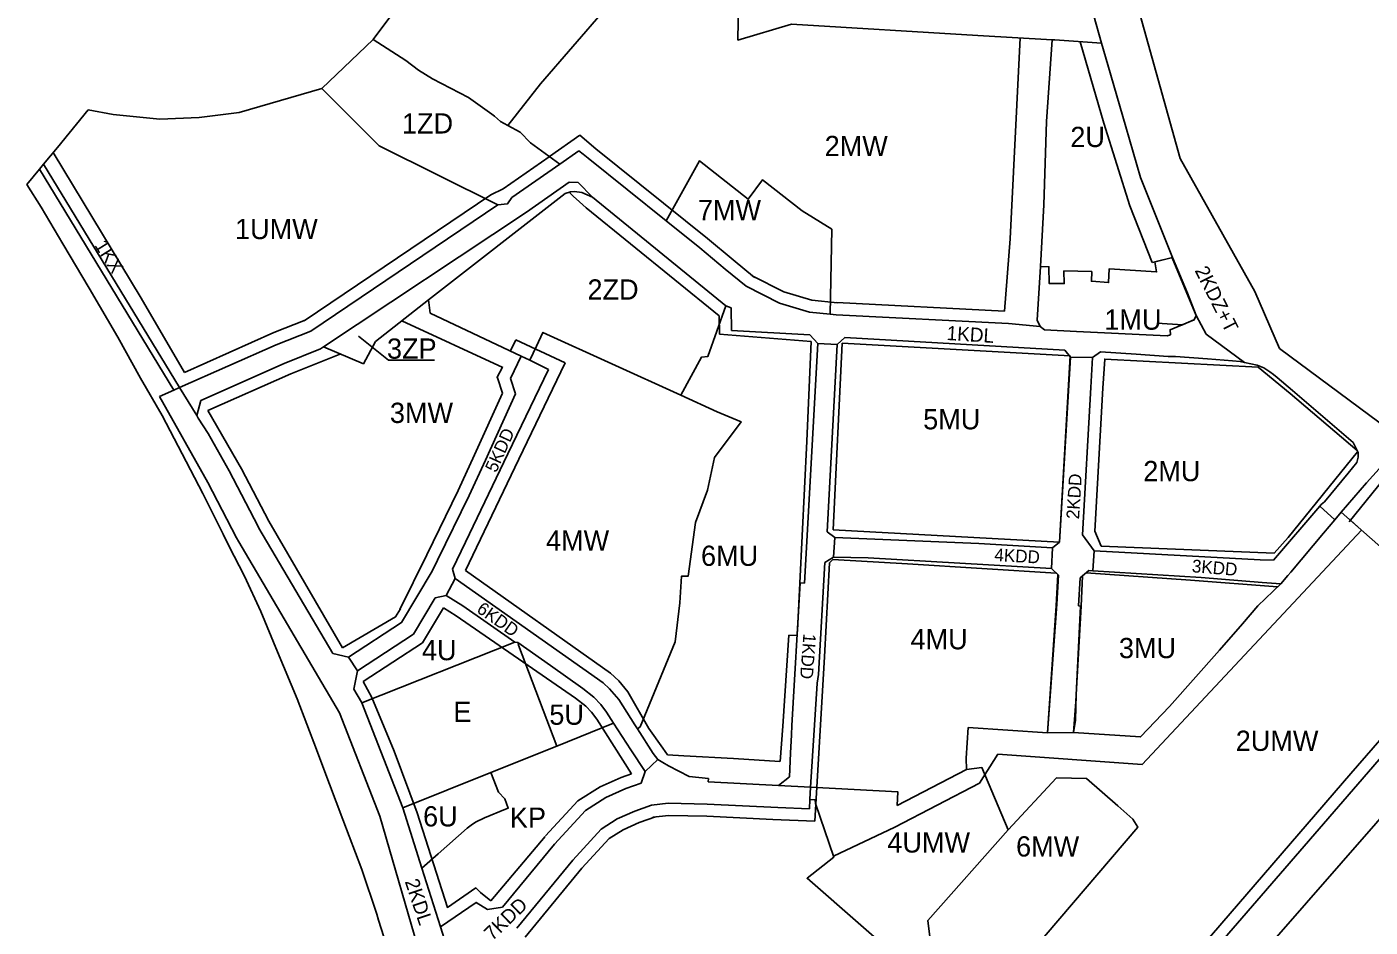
# Model space of a CAD drawing. Extents: x 7426210 to 7427579, y 5548413 to 5549685.
# Drawn here: x 7426454 to 7427118, y 5548687 to 5549132 of the extents above; entities that cross this region are included whole.
import ezdxf

# ---------------------------------------------------------------- set-up
doc = ezdxf.new("R2010")
doc.units = 0
for name, color, linetype in [('linie_rozgraniczajace', 7, 'Continuous'), ('linie_zabudowy_nieprzekraczalne', 7, 'Continuous'), ('linie_zabudowy_obowiazujace', 7, 'Continuous'), ('oznaczenia_przeznaczen', 7, 'Continuous')]:
    doc.layers.add(name, color=color, linetype=linetype)

msp = doc.modelspace()

# ---------------------------------------------------------------- linework, layer by layer
at = {"layer": 'linie_rozgraniczajace'}
for p, q in [((7426717.76, 5549064.39), (7426727.22, 5549070.95)), ((7426527.12, 5548952.75), (7426460.67, 5549061.87)), ((7426461.46, 5549043.11), (7426454.42, 5549054.29)), ((7426722.33, 5549055.38), (7426726.85, 5549055.19)), ((7426733.96, 5549047.99), (7426726.85, 5549055.19)), ((7426652.81, 5548997.28), (7426720.48, 5549049.79)), ((7426472.27, 5549025.01), (7426461.46, 5549043.11)), ((7426687.05, 5549044.16), (7426594.8, 5548981.91)), ((7426485.27, 5549003.09), (7426472.27, 5549025.01)), ((7426499.3, 5548978.86), (7426485.27, 5549003.09)), ((7426809.75, 5549004.04), (7426826.24, 5548995.73)), ((7426826.24, 5548995.73), (7426841.15, 5548991.24)), ((7426841.25, 5548980.07), (7426802.56, 5548982.08)), ((7426510.62, 5548958.68), (7426499.3, 5548978.86)), ((7426838.66, 5548857.41), (7426845.26, 5548975.81)), ((7426845.26, 5548975.81), (7426841.25, 5548980.07)), ((7426845.26, 5548975.81), (7426854.77, 5548975.24)), ((7426698.72, 5548969.45), (7426693.37, 5548958.37)), ((7426702.96, 5548967.44), (7426712.24, 5548962.96)), ((7426981.03, 5548968.79), (7426970.11, 5548968.93)), ((7426712.24, 5548962.96), (7426692.09, 5548921.26)), ((7426521.3, 5548940.19), (7426510.62, 5548958.68)), ((7426695.91, 5548950.88), (7426693.37, 5548958.37)), ((7426540.34, 5548947.65), (7426538.34, 5548940.09)), ((7426531.22, 5548921.19), (7426521.3, 5548940.19)), ((7426541.32, 5548901.7), (7426531.22, 5548921.19)), ((7426692.09, 5548921.26), (7426671.17, 5548877.55)), ((7427111.6, 5548916.93), (7427107.32, 5548911.74)), ((7427107.32, 5548911.74), (7427095.62, 5548897.58)), ((7426551.35, 5548881.59), (7426541.32, 5548901.7)), ((7427100.68, 5548888.63), (7427093.22, 5548895.38)), ((7427095.62, 5548897.58), (7427093.87, 5548896.14)), ((7427100.68, 5548888.63), (7427103.85, 5548892.38)), ((7427103.85, 5548892.38), (7427170.23, 5548833.74)), ((7426554.28, 5548875.85), (7426551.35, 5548881.59)), ((7426975.99, 5548881.15), (7426981.75, 5548873.39)), ((7426561.93, 5548860.88), (7426554.28, 5548875.85)), ((7426671.17, 5548877.55), (7426664.8, 5548864.29)), ((7426853.57, 5548879.94), (7426853.05, 5548870.2)), ((7426960.68, 5548864.59), (7426961.26, 5548874.85)), ((7426853.05, 5548870.2), (7426848.73, 5548867.55)), ((7426870.1, 5548869.79), (7426853.05, 5548870.2)), ((7426960.68, 5548864.59), (7426870.1, 5548869.79)), ((7426981.75, 5548873.39), (7426981.12, 5548863.46)), ((7427063.78, 5548868.85), (7426981.75, 5548873.39)), ((7427070.41, 5548868.79), (7427063.78, 5548868.85)), ((7426666.12, 5548859.71), (7426664.8, 5548864.29)), ((7426848.73, 5548867.55), (7426845.58, 5548812.16)), ((7426964.12, 5548861.22), (7426960.68, 5548864.59)), ((7426963.41, 5548847.03), (7426964.12, 5548861.22)), ((7426979.1, 5548863.59), (7426974.87, 5548859.97)), ((7426570.05, 5548843.37), (7426561.93, 5548860.88)), ((7426666.12, 5548859.71), (7426661.62, 5548851.3)), ((7426666.12, 5548859.71), (7426739.25, 5548808.06)), ((7426832.44, 5548787.03), (7426836.59, 5548857.53)), ((7426836.59, 5548857.53), (7426838.66, 5548857.41)), ((7426974.87, 5548859.97), (7426973.99, 5548846.1)), ((7427064.8, 5548857.72), (7427034.65, 5548860.08)), ((7427064.8, 5548857.72), (7427073.97, 5548857.02)), ((7426661.62, 5548851.3), (7426656.21, 5548850.12)), ((7426578.26, 5548823.43), (7426570.05, 5548843.37)), ((7426958.69, 5548783.49), (7426963.41, 5548847.03)), ((7426974.96, 5548846), (7426972.73, 5548798.8)), ((7426973.99, 5548846.1), (7426974.96, 5548846)), ((7426695.45, 5548828.16), (7426619.85, 5548798.2)), ((7426587.94, 5548800.28), (7426578.26, 5548823.43)), ((7426617.79, 5548814.08), (7426613.33, 5548820.73)), ((7426739.25, 5548808.06), (7426742.33, 5548805.11)), ((7426844.99, 5548807.88), (7426845.58, 5548812.16)), ((7426742.33, 5548805.11), (7426746.84, 5548799.85)), ((7426844.98, 5548807.79), (7426844.99, 5548807.88)), ((7426597.52, 5548775.14), (7426587.94, 5548800.28)), ((7426746.84, 5548799.85), (7426754.9, 5548787.34)), ((7426972.73, 5548798.8), (7426971.6, 5548783.55)), ((7426716.2, 5548776.82), (7426744.32, 5548788.26)), ((7426757.38, 5548786.32), (7426756.09, 5548785.44)), ((7426831.75, 5548773.37), (7426832.2, 5548782.47)), ((7426832.2, 5548782.47), (7426832.44, 5548787.03)), ((7426971.6, 5548783.55), (7426958.69, 5548783.49)), ((7426600.66, 5548766.86), (7426597.52, 5548775.14)), ((7426752.87, 5548774.94), (7426759.87, 5548764.39)), ((7426759.87, 5548764.39), (7426766.15, 5548770.31)), ((7426763.8, 5548773.21), (7426766.15, 5548770.31)), ((7426766.15, 5548770.31), (7426768.7, 5548768.7)), ((7426768.7, 5548768.7), (7426771.42, 5548767.16)), ((7426831.17, 5548761.72), (7426831.75, 5548773.37)), ((7426918.53, 5548770.92), (7426918.65, 5548765.3)), ((7426610.61, 5548740.55), (7426600.66, 5548766.86)), ((7426759.87, 5548764.39), (7426757.92, 5548758.55)), ((7426825.78, 5548757.39), (7426831.17, 5548761.72)), ((7426884.49, 5548747.6), (7426918.65, 5548765.3)), ((7426740.49, 5548751.49), (7426750.31, 5548755.85)), ((7426750.31, 5548755.85), (7426757.92, 5548758.55)), ((7426730.47, 5548745.13), (7426740.49, 5548751.49)), ((7426652.39, 5548661.45), (7426628.81, 5548742.31)), ((7426715.11, 5548728.46), (7426730.47, 5548745.13)), ((7426825.4, 5548746.48), (7426841.05, 5548745.82)), ((7426620, 5548715.87), (7426610.61, 5548740.55)), ((7426689.51, 5548697.37), (7426715.11, 5548728.46)), ((7426627.28, 5548693.92), (7426620, 5548715.87)), ((7426682.07, 5548696.12), (7426689.51, 5548697.37)), ((7426628.23, 5548690.91), (7426627.28, 5548693.92)), ((7426630.8, 5548682.71), (7426628.23, 5548690.91))]:
    msp.add_line(p, q, dxfattribs=at)
for points in [[(7426962.26, 5549289.73), (7427024.27, 5549067.18), (7427061.13, 5549001.37), (7427073.43, 5548973.27), (7427176.69, 5548896.63)], [(7426454.42, 5549054.29), (7426460.61, 5549061.8), (7426460.67, 5549061.87), (7426462.69, 5549064.32), (7426469.52, 5549072.6), (7426484.77, 5549091.08), (7426496.98, 5549088.91), (7426520.12, 5549086.53), (7426539.6, 5549087.43), (7426559.4, 5549089.83), (7426600.21, 5549101.71), (7426625.56, 5549125.89), (7426648.85, 5549157.31)], [(7426975.38, 5549159.04), (7426981.57, 5549137.62), (7426985.46, 5549124.17), (7426988.6, 5549113.31), (7426997.45, 5549082.71), (7427004.65, 5549057.71), (7427020.44, 5549018.16), (7427027.82, 5549000.62), (7427032.23, 5548989.61)], [(7426740.22, 5549140.87), (7426708.13, 5549104.02), (7426692.04, 5549083.48)], [(7426985.46, 5549124.17), (7426962.3, 5549125.67), (7426961.04, 5549125.75), (7426924.29, 5549127.91), (7426832.21, 5549133.53), (7426805.72, 5549125.65), (7426806.11, 5549144.19)], [(7426684.2, 5549089.06), (7426672.66, 5549097.33), (7426654.78, 5549106.46), (7426648, 5549110.74), (7426641.61, 5549115.5), (7426625.56, 5549125.89)], [(7426961.04, 5549125.75), (7426958.22, 5549085.37), (7426956.97, 5549044.24), (7426955.19, 5549013.78), (7426953.65, 5548987.32), (7426955.03, 5548984.12), (7426957.27, 5548982.52), (7426973.08, 5548981.74), (7427017.93, 5548979.45), (7427019.48, 5548980.04), (7427019.27, 5548982.5), (7427031.27, 5548987.37), (7427032.23, 5548989.61)], [(7426600.21, 5549101.71), (7426628.44, 5549073.4), (7426687.05, 5549044.16), (7426691.94, 5549044.79), (7426694.07, 5549047.79), (7426717.76, 5549064.39)], [(7426684.2, 5549089.06), (7426685.56, 5549088.09), (7426688.48, 5549085.44), (7426692.04, 5549083.48), (7426698.19, 5549080.13), (7426703.24, 5549074.83), (7426717.76, 5549064.39)], [(7426727.22, 5549070.95), (7426729.35, 5549069.31), (7426731.7, 5549067.32), (7426770.32, 5549036.39), (7426786.99, 5549023.04), (7426799.5, 5549012.47), (7426809.75, 5549004.04)], [(7426529.89, 5548953.97), (7426462.69, 5549064.32)], [(7426837.48, 5549041.19), (7426817.84, 5549056.54), (7426810.85, 5549047.01), (7426786.72, 5549065.89), (7426770.32, 5549036.39)], [(7426701.22, 5549040.59), (7426722.33, 5549055.38)], [(7426799.84, 5548994.31), (7426733.96, 5549047.99), (7426728.71, 5549050.28), (7426725.07, 5549050.87), (7426723, 5549050.66), (7426720.48, 5549049.79)], [(7426701.22, 5549040.59), (7426601.02, 5548974.03), (7426599.5, 5548973.02)], [(7426837.48, 5549041.19), (7426852.13, 5549032.15), (7426851.32, 5548990.21)], [(7427020.44, 5549018.16), (7427011.82, 5549016.12), (7427012.65, 5549011.1), (7426989.24, 5549012.63), (7426988.87, 5549005.85), (7426980.4, 5549006.51), (7426980.59, 5549011.23), (7426966.85, 5549011.61), (7426967.01, 5549005.31), (7426959.47, 5549005.39), (7426959.46, 5549013.67), (7426955.19, 5549013.78)], [(7426601.02, 5548974.03), (7426620.72, 5548965.73), (7426626.65, 5548976.69), (7426652.81, 5548997.28)], [(7426777.56, 5548950.21), (7426709.41, 5548981.25), (7426706.19, 5548974.35), (7426702.96, 5548967.44), (7426698.72, 5548969.45), (7426653.72, 5548990.76), (7426652.81, 5548997.28)], [(7426777.56, 5548950.21), (7426787.83, 5548969.05), (7426790.86, 5548969.24), (7426799.84, 5548994.31)], [(7426799.84, 5548994.31), (7426802.41, 5548993.35), (7426802.56, 5548982.08)], [(7426841.15, 5548991.24), (7426851.32, 5548990.21), (7426854.32, 5548989.91)], [(7426955.03, 5548984.12), (7426939.37, 5548985.67), (7426854.32, 5548989.91)], [(7427032.23, 5548989.61), (7427037.11, 5548980.38), (7427056.01, 5548966.38)], [(7426594.8, 5548981.91), (7426577.63, 5548975.04), (7426529.89, 5548953.97)], [(7426854.77, 5548975.24), (7426849.85, 5548882.78), (7426853.57, 5548879.94), (7426924.84, 5548876.86), (7426961.26, 5548874.85)], [(7426964.7, 5548877.55), (7426970.11, 5548968.93), (7426967.26, 5548972.4), (7426858.59, 5548978.77), (7426854.77, 5548975.24)], [(7426599.5, 5548973.02), (7426581.5, 5548965.82), (7426540.34, 5548947.65)], [(7426975.99, 5548881.15), (7426980.09, 5548953.95), (7426981.03, 5548968.79), (7426984.9, 5548971.54), (7427002.61, 5548970.45), (7427018.3, 5548969.38), (7427021.9, 5548969.26), (7427037.82, 5548968.13), (7427050.15, 5548967.25), (7427053.93, 5548966.82), (7427056.01, 5548966.38), (7427062.29, 5548965.04), (7427065.64, 5548963.72), (7427068.6, 5548961.81)], [(7427111.6, 5548916.93), (7427112.19, 5548919.56), (7427112.24, 5548921.94), (7427109.83, 5548926.8), (7427079.8, 5548952.49), (7427072.28, 5548959), (7427070.47, 5548960.39), (7427068.6, 5548961.81)], [(7426529.89, 5548953.97), (7426527.12, 5548952.75), (7426519.89, 5548949.56)], [(7426558.01, 5548879.77), (7426543.78, 5548907.12), (7426519.89, 5548949.56)], [(7426539.07, 5548938.9), (7426538.34, 5548940.09), (7426529.89, 5548953.97)], [(7426695.91, 5548950.88), (7426681.09, 5548918.18), (7426673, 5548900.62), (7426657.39, 5548868.64), (7426654.76, 5548863.29)], [(7426777.56, 5548950.21), (7426795.52, 5548942), (7426807.33, 5548937.08), (7426794.11, 5548919.45), (7426790.8, 5548903.31), (7426784.83, 5548887.35), (7426781.16, 5548860.73), (7426777.9, 5548860.84), (7426777.02, 5548847.7), (7426774.78, 5548828.39), (7426757.38, 5548786.32)], [(7426568.65, 5548885.31), (7426554.33, 5548912.84), (7426543.98, 5548931.23), (7426539.07, 5548938.9)], [(7427125.5, 5548914.1), (7427133.33, 5548907.25), (7427142.99, 5548898.8), (7427149.56, 5548893.06), (7427151.81, 5548891.16), (7427162.67, 5548882), (7427179.08, 5548867.84), (7427181.01, 5548852.4), (7427178.29, 5548845.49), (7427170.15, 5548833.9), (7427170.28, 5548833.79), (7427170.23, 5548833.74), (7427164.3, 5548826.85), (7427163.75, 5548827.34), (7427162.99, 5548826.5), (7427157.96, 5548819.2), (7427151.08, 5548803.16), (7427112.12, 5548758.07), (7427033.49, 5548667.27), (7427005.36, 5548634.62), (7426991.04, 5548617.99)], [(7427103.85, 5548892.38), (7427116.37, 5548906.9), (7427122.6, 5548913.85), (7427125.5, 5548914.1)], [(7427093.87, 5548896.14), (7427093.22, 5548895.38), (7427070.41, 5548868.79)], [(7427073.97, 5548857.02), (7427077.43, 5548861.12), (7427078.89, 5548862.85), (7427095.07, 5548881.98), (7427100.68, 5548888.63)], [(7426568.65, 5548885.31), (7426569.09, 5548884.44), (7426605.56, 5548822.56)], [(7426558.01, 5548879.77), (7426559.14, 5548877.7), (7426608.91, 5548793.23), (7426628.81, 5548742.31)], [(7426961.26, 5548874.85), (7426964.7, 5548877.55)], [(7426654.76, 5548863.29), (7426639.58, 5548837.88), (7426613.33, 5548820.73), (7426605.56, 5548822.56)], [(7427034.65, 5548860.08), (7426981.12, 5548863.46), (7426979.1, 5548863.59)], [(7427055.13, 5548837.32), (7427062.73, 5548846.13), (7427073.97, 5548857.02)], [(7426656.21, 5548850.12), (7426645.5, 5548832.19), (7426617.79, 5548814.08), (7426615.96, 5548804.91)], [(7426695.45, 5548828.16), (7426669.83, 5548846.23), (7426661.62, 5548851.3)], [(7427214.1, 5548847.4), (7427175.3, 5548800.83), (7427120.9, 5548738.6), (7427069.59, 5548679.9)], [(7426971.6, 5548783.55), (7427004.72, 5548781.37), (7427019.06, 5548796.49), (7427043.66, 5548824.27), (7427055.13, 5548837.32)], [(7426752.87, 5548774.94), (7426744.32, 5548788.26), (7426740.89, 5548793.67), (7426737.96, 5548797.48), (7426734.6, 5548800.97), (7426729.19, 5548805.27), (7426713.13, 5548816.66), (7426697.06, 5548828.05), (7426695.45, 5548828.16)], [(7426697.06, 5548828.05), (7426697.42, 5548826.71)], [(7426697.42, 5548826.71), (7426716.2, 5548776.82), (7426683.68, 5548763.77), (7426640.13, 5548746.31)], [(7426615.96, 5548804.91), (7426619.74, 5548798.49), (7426619.85, 5548798.2), (7426640.13, 5548746.31)], [(7426844.98, 5548807.79), (7426841.65, 5548756.55), (7426884.85, 5548754.2), (7426884.49, 5548747.6)], [(7426754.9, 5548787.34), (7426756.09, 5548785.44), (7426763.8, 5548773.21)], [(7426918.53, 5548770.92), (7426919.58, 5548786.01), (7426958.69, 5548783.49)], [(7426649.57, 5548716.59), (7426657.57, 5548723.6), (7426671.95, 5548736.37), (7426673.99, 5548737.82), (7426676.04, 5548739.27), (7426680.53, 5548741.46), (7426690.98, 5548745.72), (7426692.31, 5548746.26), (7426690.51, 5548750.82), (7426687.49, 5548754.16), (7426683.68, 5548763.77)], [(7426771.42, 5548767.16), (7426776.6, 5548764.43), (7426781.6, 5548761.92), (7426791.15, 5548760.8), (7426791.08, 5548759.22)], [(7426918.65, 5548765.3), (7426926.31, 5548766.21), (7426939.27, 5548735.51), (7426899.66, 5548690.67), (7426901.57, 5548674.58), (7426892.99, 5548665.11)], [(7426791.08, 5548759.22), (7426825.78, 5548757.39), (7426841.65, 5548756.55)], [(7426841.65, 5548756.55), (7426841.31, 5548750.46), (7426841.05, 5548745.82)], [(7426939.27, 5548735.51), (7426963.14, 5548761.15), (7426977.92, 5548760.9), (7426993.46, 5548747.35), (7427000.95, 5548740.85)], [(7426825.4, 5548746.48), (7426790.53, 5548748.23), (7426771.25, 5548748.61), (7426763.06, 5548747.64)], [(7426841.31, 5548750.46), (7426843.94, 5548750.31), (7426844.06, 5548748.51), (7426853.17, 5548722.04), (7426839.96, 5548711.56), (7426892.99, 5548665.11), (7426914.38, 5548645.99)], [(7426667.6, 5548659.8), (7426658.78, 5548687.58), (7426649.57, 5548716.59), (7426640.13, 5548746.31)], [(7426696.44, 5548686.9), (7426724.16, 5548720.58), (7426738.22, 5548735.84), (7426746.17, 5548740.88), (7426754.76, 5548744.7), (7426763.06, 5548747.64)], [(7427000.95, 5548740.85), (7427003.3, 5548736.82), (7426951.39, 5548675.84), (7426938.43, 5548660.61), (7426932.94, 5548654.17), (7426930.13, 5548658.69), (7426914.38, 5548645.99)], [(7426682.07, 5548696.12), (7426676.37, 5548699.62), (7426658.78, 5548687.58)]]:
    msp.add_lwpolyline(points, dxfattribs=at)
at = {"layer": 'linie_zabudowy_nieprzekraczalne'}
for p, q in [((7426712.61, 5549068.12), (7426727.7, 5549078.57)), ((7426591.44, 5548986.88), (7426683.7, 5549049.13)), ((7427020.44, 5549018.16), (7427010.6, 5549015.82)), ((7426689.53, 5548963.82), (7426639.73, 5548986.99)), ((7426693.32, 5548972.06), (7426695.98, 5548977.56)), ((7426695.96, 5548977.55), (7426720.47, 5548966.2)), ((7426842.01, 5548976.8), (7426796.58, 5548980.29)), ((7426857.22, 5548975.85), (7426852.88, 5548883.7)), ((7426686.6, 5548958.82), (7426689.45, 5548963.97)), ((7426720.47, 5548966.2), (7426697.49, 5548918.65)), ((7426689.46, 5548951.2), (7426686.9, 5548958.77)), ((7426697.5, 5548918.67), (7426676.59, 5548874.96)), ((7427124.63, 5548908.44), (7427107.73, 5548887.67)), ((7427108.36, 5548888.4), (7427113.84, 5548883.52)), ((7426852.88, 5548883.7), (7426964.7, 5548877.55)), ((7427113.8, 5548883.48), (7427005.55, 5548767.79)), ((7426676.58, 5548874.95), (7426671.1, 5548863.54)), ((7426985.19, 5548875.65), (7427070.89, 5548872.21)), ((7426671.1, 5548863.54), (7426742.72, 5548812.97)), ((7426742.72, 5548812.97), (7426746.88, 5548809.02)), ((7426746.88, 5548809.02), (7426751.4, 5548803.75)), ((7426751.4, 5548803.75), (7426761.78, 5548785.62)), ((7426761.78, 5548785.54), (7426768.72, 5548775.76)), ((7427005.55, 5548767.79), (7426934.25, 5548772.85)), ((7426748.09, 5548761.43), (7426753.1, 5548763.21)), ((7426726.59, 5548749.78), (7426737.65, 5548756.79)), ((7426737.65, 5548756.79), (7426748.09, 5548761.43)), ((7426710.7, 5548732.53), (7426726.59, 5548749.78)), ((7426843.81, 5548739.74), (7426822.99, 5548740.59)), ((7426683.6, 5548700.47), (7426710.48, 5548732.27))]:
    msp.add_line(p, q, dxfattribs=at)
for points in [[(7426937.41, 5548991.77), (7426940.32, 5549027.36), (7426945.25, 5549126.66)], [(7427010.43, 5549015.82), (7426999.46, 5549043.81), (7426986.53, 5549084.53), (7426974.92, 5549124.75)], [(7426727.7, 5549078.57), (7426735.52, 5549071.95), (7426790.8, 5549027.67), (7426803.34, 5549017.08), (7426813.92, 5549008.38)], [(7426467.43, 5549070.06), (7426510.88, 5548998.1), (7426532.27, 5548961.45)], [(7426683.7, 5549049.13), (7426689.78, 5549052.1), (7426712.49, 5549068.02)], [(7426796.46, 5548989.33), (7426730.81, 5549042.82), (7426727.42, 5549045.68), (7426724.36, 5549048.49), (7426722.14, 5549050.69)], [(7427032.59, 5548988.75), (7427020.34, 5549018.13)], [(7426812.78, 5549009.12), (7426828.46, 5549001.33), (7426842.33, 5548997.15), (7426854.92, 5548995.88)], [(7426854.62, 5548995.91), (7426937.41, 5548991.77)], [(7426532.27, 5548961.45), (7426576.46, 5548981.17), (7426591.98, 5548987.2)], [(7426796.58, 5548980.32), (7426796.46, 5548989.33)], [(7427012.85, 5548985.77), (7427025.35, 5548985.02), (7427031.33, 5548987.51)], [(7426834.84, 5548831.37), (7426835.2, 5548833.95), (7426839.82, 5548927.54), (7426841.96, 5548976.77)], [(7426964.7, 5548877.55), (7426969.87, 5548969.6), (7426857.27, 5548975.84)], [(7426609.49, 5548970.68), (7426584.88, 5548960.77), (7426543.87, 5548942.57)], [(7427062.86, 5548964.06), (7426987, 5548968.05), (7426986.08, 5548953.59), (7426982.09, 5548883), (7426985.19, 5548875.65)], [(7427111.66, 5548922.86), (7427078.59, 5548951.04), (7427062.86, 5548964.06)], [(7426638.76, 5548844.29), (7426652, 5548871.28), (7426667.58, 5548903.19), (7426675.64, 5548920.67), (7426689.46, 5548951.2)], [(7426543.87, 5548942.57), (7426560.43, 5548913.88), (7426574, 5548888.02), (7426610.42, 5548825.43)], [(7427070.8, 5548872.23), (7427077.58, 5548879.96), (7427111.94, 5548922.24)], [(7426962.97, 5548862.35), (7426889.52, 5548866.95), (7426852.68, 5548869.08), (7426850.94, 5548867.34), (7426848.48, 5548821)], [(7426958.69, 5548783.49), (7426962.99, 5548846.09), (7426963.78, 5548861.55)], [(7427072.42, 5548855.51), (7427029.37, 5548858.91), (7426977.86, 5548862.53)], [(7426976.02, 5548860.96), (7426975.31, 5548845.98), (7426972.9, 5548802.41), (7426972.53, 5548789.61), (7426971.6, 5548783.55)], [(7426610.42, 5548825.43), (7426636.61, 5548840.71), (7426638.99, 5548844.72)], [(7426660.21, 5548845.12), (7426649.94, 5548827.93), (7426620.61, 5548808.76)], [(7426725.58, 5548800.48), (7426666.53, 5548841.22), (7426660.21, 5548845.12)], [(7426826.67, 5548769.26), (7426827.92, 5548786.63), (7426830.92, 5548831.58), (7426835.05, 5548831.45)], [(7426848.48, 5548821), (7426843.81, 5548739.74)], [(7426620.61, 5548808.76), (7426624.85, 5548800.93), (7426635.97, 5548774.4), (7426647.29, 5548743.94), (7426662.2, 5548697.18), (7426676.19, 5548706.77), (7426678.61, 5548704.51), (7426683.6, 5548700.47)], [(7426753.1, 5548763.21), (7426735.97, 5548790.23), (7426733.41, 5548793.56), (7426730.55, 5548796.52), (7426725.58, 5548800.48)], [(7426768.72, 5548775.76), (7426770.98, 5548772.51), (7426779.08, 5548771.98), (7426803.57, 5548770.67), (7426826.48, 5548769.31)], [(7426934.25, 5548772.85), (7426925.08, 5548758.54), (7426883.27, 5548736.85), (7426853.03, 5548722.44)], [(7426765.07, 5548741.99), (7426756.99, 5548739.12), (7426749.01, 5548735.57), (7426742.1, 5548731.2), (7426728.69, 5548716.63), (7426700.63, 5548682.56)], [(7426822.99, 5548740.59), (7426790.32, 5548742.24), (7426771.54, 5548742.6), (7426763.77, 5548741.69)]]:
    msp.add_lwpolyline(points, dxfattribs=at)
at = {"layer": 'linie_zabudowy_obowiazujace'}
msp.add_lwpolyline([(7426999.5, 5548637.91), (7427031.6, 5548673.89), (7427108.64, 5548763.35), (7427150.54, 5548811.58)], dxfattribs=at)
at = {"layer": 'oznaczenia_przeznaczen'}
msp.add_lwpolyline([(7426655.82, 5548967.51), (7426633.16, 5548967.51), (7426618.3, 5548979.34)], dxfattribs=at)

# ---------------------------------------------------------------- texts
for s, p in [('1ZD', (7426639.75, 5549079.47)), ('2U', (7426970.01, 5549072.78)), ('2MW', (7426848.61, 5549068.3)), ('7MW', (7426785.98, 5549036.65)), ('1UMW', (7426557.28, 5549027.29)), ('2ZD', (7426731.42, 5548997.41)), ('1MU', (7426986.81, 5548982.54)), ('3ZP', (7426632.36, 5548968.22)), ('3MW', (7426633.81, 5548936.48)), ('5MU', (7426897.29, 5548933.32)), ('2MU', (7427006.04, 5548907.73)), ('4MW', (7426710.94, 5548873.44)), ('6MU', (7426787.53, 5548865.89)), ('4MU', (7426891.05, 5548824.67)), ('4U', (7426649.63, 5548819.28)), ('3MU', (7426994.02, 5548820.31)), ('E', (7426665.15, 5548788.77)), ('5U', (7426712.58, 5548787.4)), ('2UMW', (7427051.74, 5548774.5)), ('6U', (7426650.2, 5548737.17)), ('KP', (7426693.09, 5548736.5)), ('4UMW', (7426879.59, 5548724.27)), ('6MW', (7426943.19, 5548722.32))]:
    msp.add_text(s, height=10, dxfattribs=at).set_placement(p)
for s, height, rotation, p in [('1KX', 6.79, 301.88516, (7426487.62, 5549024.25)), ('2KDZ+T', 7, 296.66073, (7427031.32, 5549011.84)), ('1KDL', 7, 356.35908, (7426908.73, 5548977.49)), ('5KDD', 6.3, 65.46481, (7426686.28, 5548911.6)), ('2KDD', 6.3, 86.40749, (7426974.3, 5548888.83)), ('4KDD', 6.3, 356.72531, (7426932.35, 5548868.31)), ('3KDD', 6.3, 355.25964, (7427029.87, 5548862.79)), ('6KDD', 6.3, 324.97333, (7426676.21, 5548843.35)), ('1KDD', 6.3, 265.65701, (7426838.14, 5548832.6)), ('2KDL', 7, 288.42059, (7426641.11, 5548710.01)), ('7KDD', 7, 43.90384, (7426684.42, 5548680.36))]:
    msp.add_text(s, height=height, rotation=rotation, dxfattribs=at).set_placement(p)

doc.saveas('drawing.dxf')
